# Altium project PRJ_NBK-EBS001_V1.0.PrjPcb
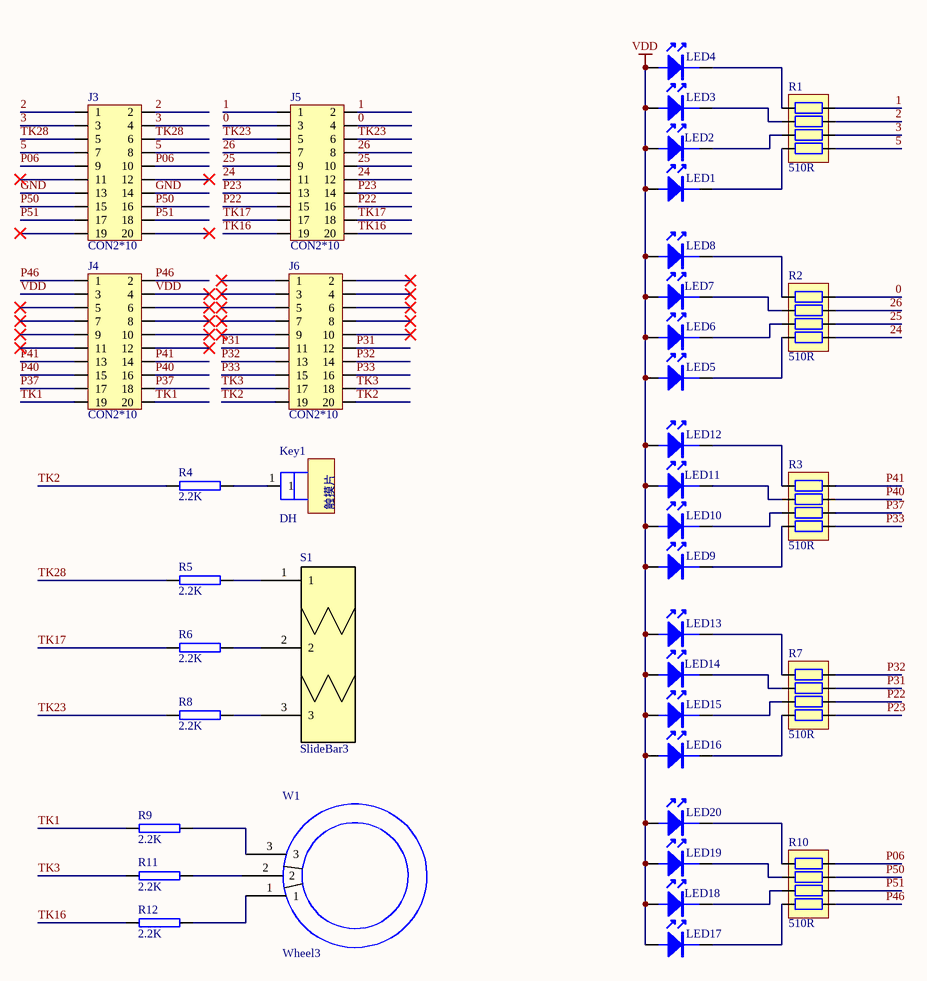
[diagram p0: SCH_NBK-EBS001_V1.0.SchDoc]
1 sheet, 39 parts. Net scope: global (net labels, ports and power ports of the same name join across sheets).
Board file: PCB_NBK-EBS001_V1.0.PcbDoc

## Sheet SCH_NBK-EBS001_V1.0.SchDoc
size A4; DocumentNumber: 1; SheetNumber: 1; SheetTotal: 1

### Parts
J3  CON2*10  [TP-2.54-10P]
J4  CON2*10  [TP-2.54-10P]
J5  CON2*10  [TP-2.54-10P]
J6  CON2*10  [TP-2.54-10P]
Key1  DH  [TK PAD-3]
LED1  LS-SP170UHR24  [LED1206]  (value not drawn)
LED2  LS-SP170UHR24  [LED1206]  (value not drawn)
LED3  LS-SP170UHR24  [LED1206]  (value not drawn)
LED4  LS-SP170UHR24  [LED1206]  (value not drawn)
LED5  LS-SP170UHR24  [LED1206]  (value not drawn)
LED6  LS-SP170UHR24  [LED1206]  (value not drawn)
LED7  LS-SP170UHR24  [LED1206]  (value not drawn)
LED8  LS-SP170UHR24  [LED1206]  (value not drawn)
LED9  LS-SP170UHR24  [LED1206]  (value not drawn)
LED10  LS-SP170UHR24  [LED1206]  (value not drawn)
LED11  LS-SP170UHR24  [LED1206]  (value not drawn)
LED12  LS-SP170UHR24  [LED1206]  (value not drawn)
LED13  LS-SP170UHR24  [LED1206]  (value not drawn)
LED14  LS-SP170UHR24  [LED1206]  (value not drawn)
LED15  LS-SP170UHR24  [LED1206]  (value not drawn)
LED16  LS-SP170UHR24  [LED1206]  (value not drawn)
LED17  LS-SP170UHR24  [LED1206]  (value not drawn)
LED18  LS-SP170UHR24  [LED1206]  (value not drawn)
LED19  LS-SP170UHR24  [LED1206]  (value not drawn)
LED20  LS-SP170UHR24  [LED1206]  (value not drawn)
R1  510R  [RCA-8P4R-0603]
R2  510R  [RCA-8P4R-0603]
R3  510R  [RCA-8P4R-0603]
R4  2.2K  [R0805]
R5  2.2K  [R0805]
R6  2.2K  [R0805]
R7  510R  [RCA-8P4R-0603]
R8  2.2K  [R0805]
R9  2.2K  [R0805]
R10  510R  [RCA-8P4R-0603]
R11  2.2K  [R0805]
R12  2.2K  [R0805]
S1  SlideBar3  [PCBCOMPONENT_1 - duplicate]
W1  Wheel3  [滑轮10-18-3]

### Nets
VDD: J4.3 J4.4 LED1.1 LED2.1 LED3.1 LED4.1 LED5.1 LED6.1 LED7.1 LED8.1 LED9.1 LED10.1 LED11.1 LED12.1 LED13.1 LED14.1 LED15.1 LED16.1 LED17.1 LED18.1 LED19.1 LED20.1
0: J5.3 J5.4 R2.8
1: J5.1 J5.2 R1.8
2: J3.1 J3.2 R1.7
3: J3.3 J3.4 R1.6
5: J3.7 J3.8 R1.5
24: J5.11 J5.12 R2.5
25: J5.9 J5.10 R2.6
26: J5.7 J5.8 R2.7
GND: J3.13 J3.14
P06: J3.9 J3.10 R10.8
P22: J5.15 J5.16 R7.6
P23: J5.13 J5.14 R7.5
P31: J6.11 J6.12 R7.7
P32: J6.13 J6.14 R7.8
P33: J6.15 J6.16 R3.5
P37: J4.17 J4.18 R3.6
P40: J4.15 J4.16 R3.7
P41: J4.13 J4.14 R3.8
P46: J4.1 J4.2 R10.5
P50: J3.15 J3.16 R10.7
P51: J3.17 J3.18 R10.6
TK1: J4.19 J4.20 R9.2
TK2: J6.19 J6.20 R4.2
TK3: J6.17 J6.18 R11.2
TK16: J5.19 J5.20 R12.2
TK17: J5.17 J5.18 R6.2
TK23: J5.5 J5.6 R8.2
TK28: J3.5 J3.6 R5.2
NetKey1_1: Key1.1 R4.1
NetLED1_2: LED1.2 R1.4
NetLED2_2: LED2.2 R1.3
NetLED3_2: LED3.2 R1.2
NetLED4_2: LED4.2 R1.1
NetLED5_2: LED5.2 R2.4
NetLED6_2: LED6.2 R2.3
NetLED7_2: LED7.2 R2.2
NetLED8_2: LED8.2 R2.1
NetLED9_2: LED9.2 R3.4
NetLED10_2: LED10.2 R3.3
NetLED11_2: LED11.2 R3.2
NetLED12_2: LED12.2 R3.1
NetLED13_2: LED13.2 R7.1
NetLED14_2: LED14.2 R7.2
NetLED15_2: LED15.2 R7.3
NetLED16_2: LED16.2 R7.4
NetLED17_2: LED17.2 R10.4
NetLED18_2: LED18.2 R10.3
NetLED19_2: LED19.2 R10.2
NetLED20_2: LED20.2 R10.1
NetR5_1: R5.1 S1.1
NetR6_1: R6.1 S1.2
NetR8_1: R8.1 S1.3
NetR9_1: R9.1 W1.3
NetR11_1: R11.1 W1.2
NetR12_1: R12.1 W1.1

Not connected (* = marked no-connect by the designer): J3 11* 12* 19* 20*; J4 5* 6* 7* 8* 9* 10* 11* 12*; J6 1* 2* 3* 4* 5* 6* 7* 8* 9* 10*

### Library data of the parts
LED1-LED20 = LED-LS-SP170UHR24: 绿色；贴片
R1-R3 R7 R10 = R-8P4R: 贴片排阻; BOM名称: 贴片网络排阻; 版权归属: 封装库来自淘宝 ID：黄晶宝石
R4-R6 R8 R9 R11 R12 = R0805: 功率: 1/8W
